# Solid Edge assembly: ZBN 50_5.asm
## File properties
Title: Zylinder
Author: bmolnar
Template: iso metric assembly.asm
Last saved by: bmolnar
Revision: 6
Application: Solid Edge
Username: bmolnar
Dokumentum tartalom típus: 1
Document Number: ZBN 50/5
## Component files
Profilrohr.par
Kolbenstange.par
Kit_2.par
Kit_1.par
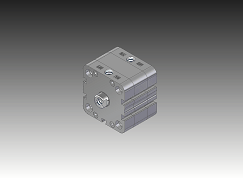
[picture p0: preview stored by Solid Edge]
